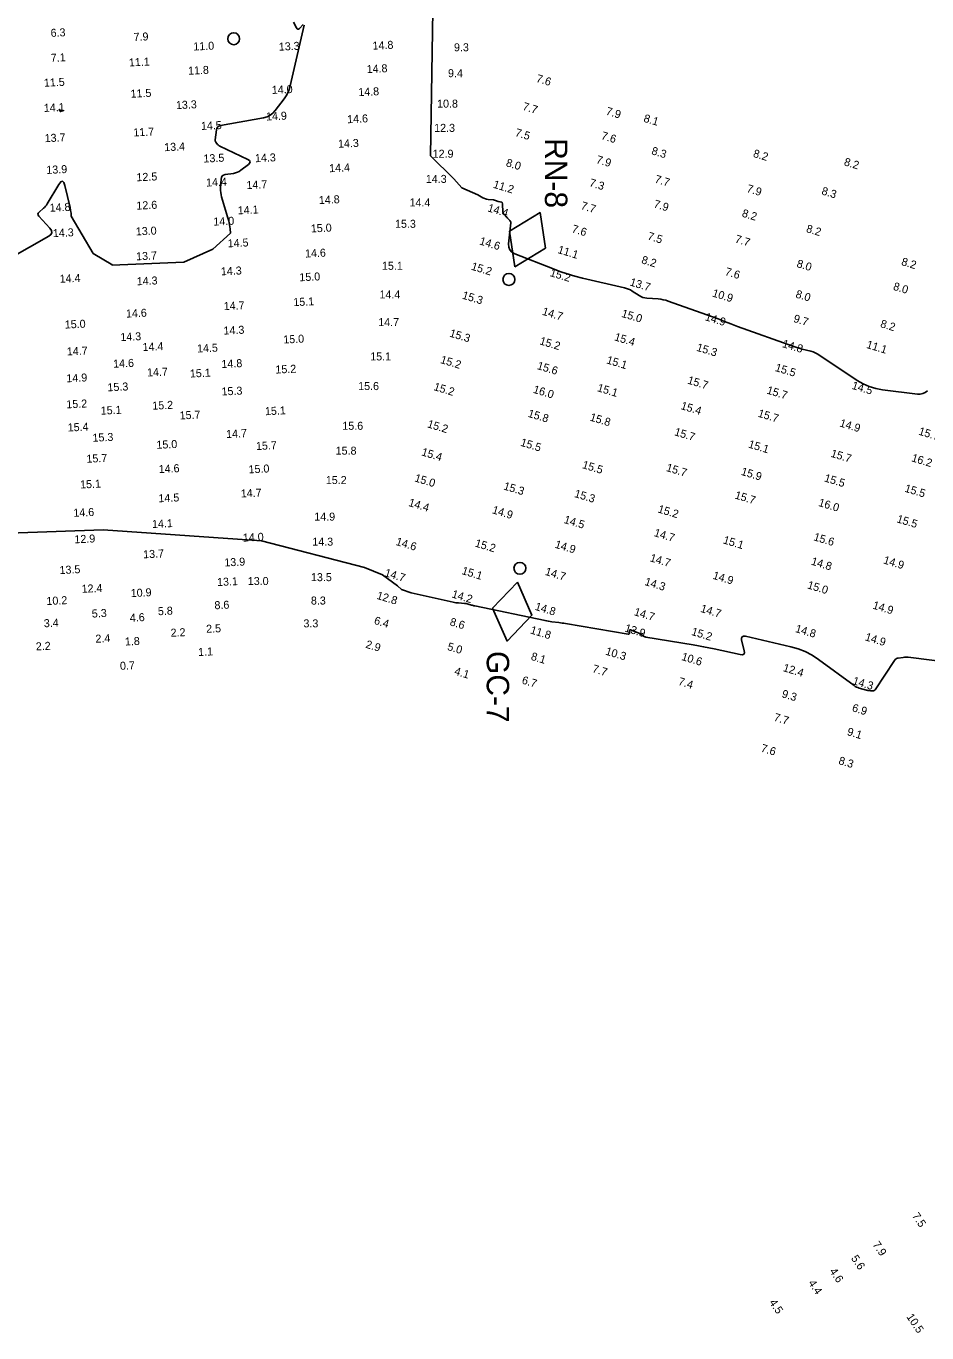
# Model space of a CAD drawing. Extents: x 824616 to 827440, y 158441 to 163197.
# Drawn here: x 825520 to 826082, y 160899 to 161716 of the extents above; entities that cross this region are included whole.
import ezdxf

# ---------------------------------------------------------------- set-up
doc = ezdxf.new("R2010")
doc.units = 0
for name, color, linetype in [('V-CHAN-CONT-EL14', 7, 'Continuous'), ('V-CHAN-NAID', 7, 'Continuous'), ('V-TOPO-SOUN', 7, 'Continuous')]:
    doc.layers.add(name, color=color, linetype=linetype)

msp = doc.modelspace()

# ---------------------------------------------------------------- linework, layer by layer
at = {"layer": 'V-CHAN-CONT-EL14'}
for points in [[(826082.79, 161487.77), (826081.39, 161486.66), (826079.87, 161485.94), (826078.21, 161485.6), (826076.43, 161485.64), (826054.58, 161488.39), (826050.41, 161489.15), (826046.4, 161490.38), (826042.58, 161492.07), (826038.92, 161494.22), (826014.97, 161510.16), (826013.79, 161510.88), (826012.55, 161511.49), (826011.27, 161512), (826009.94, 161512.4), (826004.53, 161513.78), (826003.18, 161514.14), (826001.85, 161514.53), (826000.52, 161514.95), (825999.2, 161515.4), (825964, 161527.9), (825962.99, 161528.26), (825961.99, 161528.64), (825960.99, 161529.03), (825959.99, 161529.44), (825956.02, 161531.08), (825955.02, 161531.48), (825954.02, 161531.87), (825953.02, 161532.25), (825952.01, 161532.62), (825920.83, 161543.77), (825919.29, 161544.26), (825917.74, 161544.64), (825916.16, 161544.91), (825914.56, 161545.08), (825907.5, 161545.57), (825906.22, 161545.73), (825904.99, 161546.06), (825903.81, 161546.54), (825902.68, 161547.18), (825898.27, 161550.03), (825897.15, 161550.7), (825895.98, 161551.26), (825894.77, 161551.71), (825893.51, 161552.06), (825867.23, 161558.18), (825862.45, 161559.39), (825857.73, 161560.77), (825853.06, 161562.32), (825848.44, 161564.05), (825824.94, 161573.32), (825823.08, 161574.35), (825821.82, 161575.75), (825821.16, 161577.51), (825821.1, 161579.64), (825822.45, 161592.64), (825822.45, 161593.06), (825822.37, 161593.44), (825822.19, 161593.79), (825821.93, 161594.11), (825820.72, 161595.34), (825820.42, 161595.65), (825820.12, 161595.96), (825819.82, 161596.26), (825819.52, 161596.57), (825818.27, 161597.85), (825818, 161598.18), (825817.8, 161598.54), (825817.66, 161598.94), (825817.6, 161599.36), (825817.3, 161604.5), (825817.19, 161605.27), (825816.95, 161605.57), (825816.6, 161605.59), (825815.82, 161605.69), (825814.6, 161605.98), (825813.01, 161606.53), (825811.65, 161607.12), (825808.44, 161607.29), (825807.26, 161607.53), (825805.1, 161608.2), (825801.95, 161610.13), (825791.96, 161614.57), (825786.92, 161620.15), (825772.26, 161634.63), (825774.83, 161790.45)], [(825693.47, 161716.14), (825684.63, 161678.21), (825684, 161676.04), (825683.16, 161673.96), (825682.11, 161671.99), (825680.84, 161670.11), (825675.33, 161662.81), (825673.84, 161661.16), (825672.14, 161659.87), (825670.22, 161658.93), (825668.08, 161658.35), (825641.25, 161653.49), (825640.22, 161653.16), (825639.45, 161652.59), (825638.92, 161651.79), (825638.64, 161650.74), (825637.86, 161644.61), (825637.84, 161644.19), (825637.91, 161643.8), (825638.06, 161643.43), (825638.29, 161643.08), (825639.36, 161641.72), (825639.65, 161641.4), (825639.96, 161641.12), (825640.3, 161640.88), (825640.68, 161640.67), (825658.23, 161632.21), (825659.21, 161631.56), (825659.59, 161630.85), (825659.38, 161630.07), (825658.56, 161629.22), (825653.92, 161625.55), (825652.87, 161624.82), (825651.75, 161624.26), (825650.57, 161623.84), (825649.31, 161623.59), (825644.17, 161622.87), (825643.04, 161622.56), (825642.21, 161621.96), (825641.69, 161621.08), (825641.48, 161619.92), (825641.2, 161614.25), (825641.2, 161612.88), (825641.3, 161611.52), (825641.53, 161610.18), (825641.87, 161608.85), (825645.59, 161596.47), (825646.27, 161593.95), (825646.81, 161591.41), (825647.2, 161588.84), (825647.45, 161586.24), (825636.27, 161576.11), (825618.25, 161568.05), (825573.33, 161566.25)], [(825686.71, 161718.01), (825688.55, 161714.5), (825688.95, 161713.94), (825689.4, 161713.71), (825689.89, 161713.8), (825690.44, 161714.22), (825692.7, 161716.56)], [(825509.88, 161570.53), (825533.84, 161584.26), (825535.2, 161585.32), (825535.79, 161586.51), (825535.6, 161587.82), (825534.63, 161589.25), (825527.73, 161596.89), (825527.28, 161597.54), (825527.16, 161598.18), (825527.36, 161598.79), (825527.88, 161599.39), (825530.61, 161601.73), (825531.26, 161602.34), (825531.86, 161602.99), (825532.4, 161603.69), (825532.89, 161604.44), (825540.09, 161616.57), (825541.35, 161618.24), (825542.42, 161618.7), (825543.3, 161617.94), (825543.99, 161615.96), (825547.18, 161602.17), (825547.54, 161600.41), (825547.79, 161598.63), (825547.93, 161596.85), (825561.71, 161573.54), (825573.89, 161566.27)], [(825509.14, 161398.75), (825567.91, 161400.83), (825666.87, 161393.96), (825731.09, 161377.23), (825742.31, 161372.73), (825751.81, 161365.88), (825754.26, 161363.51), (825760.32, 161361.35), (825786.55, 161355.55), (825787.35, 161355.39), (825788.16, 161355.25), (825788.97, 161355.15), (825789.79, 161355.08), (825793.59, 161354.82), (825794.14, 161354.77), (825794.69, 161354.69), (825795.22, 161354.57), (825795.76, 161354.42), (825797.88, 161353.77), (825798.42, 161353.62), (825798.95, 161353.47), (825799.49, 161353.34), (825800.03, 161353.22), (825843.88, 161344.07), (825844.95, 161343.86), (825846.01, 161343.68), (825847.08, 161343.51), (825848.16, 161343.37), (825852.46, 161342.85), (825853.54, 161342.71), (825854.61, 161342.56), (825855.68, 161342.4), (825856.75, 161342.23), (825895.89, 161335.66), (825896.21, 161335.66), (825896.43, 161335.75), (825896.57, 161335.96), (825896.61, 161336.27), (825896.62, 161337.73), (825896.67, 161338.03), (825896.79, 161338.21), (825897.01, 161338.27), (825897.31, 161338.2), (825903.01, 161336), (825903.35, 161335.85), (825903.68, 161335.68), (825903.99, 161335.48), (825904.29, 161335.26), (825905.46, 161334.34), (825905.76, 161334.13), (825906.08, 161333.96), (825906.42, 161333.83), (825906.78, 161333.75), (825936.35, 161328.85), (825939.64, 161328.29), (825942.92, 161327.69), (825946.2, 161327.04), (825949.47, 161326.36), (825965.82, 161322.87), (825967.19, 161322.76), (825968.05, 161323.15), (825968.41, 161324.02), (825968.27, 161325.38), (825966.68, 161331.8), (825966.54, 161333.16), (825966.9, 161334.02), (825967.75, 161334.39), (825969.11, 161334.27), (825997.31, 161327.76), (826001.97, 161326.44), (826006.43, 161324.66), (826010.68, 161322.44), (826014.72, 161319.77), (826036.96, 161303.44), (826037.68, 161302.96), (826038.43, 161302.54), (826039.22, 161302.2), (826040.04, 161301.93), (826044.62, 161300.62), (826044.85, 161300.56), (826045.08, 161300.51), (826045.31, 161300.47), (826045.55, 161300.44), (826046.48, 161300.32), (826046.72, 161300.3), (826046.95, 161300.28), (826047.19, 161300.27), (826047.42, 161300.27), (826049.06, 161300.27), (826049.39, 161300.31), (826049.69, 161300.42), (826049.94, 161300.6), (826050.15, 161300.86), (826062.13, 161319.16), (826062.6, 161319.74), (826063.15, 161320.18), (826063.79, 161320.49), (826064.51, 161320.67), (826067.58, 161321.09), (826068.34, 161321.17), (826069.11, 161321.2), (826069.88, 161321.18), (826070.65, 161321.11), (826098.51, 161317.75)]]:
    msp.add_lwpolyline(points, dxfattribs=at)
msp.add_lwpolyline([(825541.08, 161662.35), (825541.02, 161662.39), (825540.97, 161662.46), (825540.48, 161663.35), (825540.45, 161663.42), (825540.45, 161663.45), (825540.49, 161663.45), (825540.55, 161663.41), (825540.88, 161663.19), (825540.97, 161663.14), (825541.06, 161663.1), (825541.15, 161663.07), (825541.25, 161663.05), (825542.78, 161662.86), (825542.91, 161662.83), (825542.96, 161662.8), (825542.92, 161662.77), (825542.79, 161662.73), (825541.95, 161662.54), (825541.86, 161662.52), (825541.77, 161662.5), (825541.68, 161662.47), (825541.59, 161662.45), (825541.23, 161662.35), (825541.15, 161662.34)], close=True, dxfattribs=at)
at = {"layer": 'V-CHAN-NAID'}
for points in [[(825824.99, 161565.19), (825844.19, 161576.87), (825840.79, 161599.09), (825821.59, 161587.41)], [(825826.63, 161368.15), (825811.11, 161351.89), (825820.14, 161331.31), (825835.66, 161347.56)]]:
    msp.add_lwpolyline(points, close=True, dxfattribs=at)
for centre in [(825649.39, 161707.71), (825821.3, 161557.28), (825828.15, 161376.74)]:
    msp.add_circle(centre, 3.74, dxfattribs=at)

# ---------------------------------------------------------------- texts
for s, p in [('RN-8', (825843.82, 161645.57)), ('GC-7', (825807.45, 161325.06))]:
    msp.add_text(s, height=14, rotation=270, dxfattribs=at).set_placement(p)
at = {"layer": 'V-TOPO-SOUN'}
for s, rotation, p in [('6.3', 2.7, (825535.17, 161708.85)), ('7.9', 2.7, (825586.99, 161706.3)), ('11.0 ', 2.7, (825624.29, 161700.32)), ('13.3 ', 2.7, (825677.68, 161700.24)), ('14.8 ', 2.7, (825736.25, 161700.88)), ('7.1', 2.7, (825535.24, 161693.25)), ('11.1 ', 2.7, (825584.04, 161690.39)), ('11.8 ', 2.7, (825621.01, 161685.21)), ('14.8 ', 2.7, (825732.57, 161686.23)), ('11.5 ', 2.7, (825530.96, 161677.7)), ('7.6', 343.2, (825837.95, 161680.85)), ('11.5 ', 2.7, (825585.09, 161670.83)), ('14.0 ', 2.7, (825673.32, 161673.21)), ('14.8 ', 2.7, (825727.33, 161671.83)), ('14.1 ', 2.7, (825530.91, 161661.96)), ('13.3 ', 2.7, (825613.45, 161663.69)), ('7.7', 343.2, (825829.48, 161663.39)), ('7.9', 343.2, (825881.51, 161660.43)), ('14.5 ', 2.7, (825629.05, 161650.7)), ('14.9 ', 2.7, (825669.71, 161656.58)), ('14.6 ', 2.7, (825720.38, 161654.89)), ('8.1', 343.2, (825905.07, 161655.96)), ('13.7 ', 2.7, (825531.45, 161643.05)), ('11.7 ', 2.7, (825586.79, 161646.63)), ('7.5', 343.2, (825824.81, 161647.04)), ('7.6', 343.2, (825878.57, 161645.08)), ('13.4 ', 2.7, (825606.11, 161637.41)), ('14.3 ', 2.7, (825714.67, 161639.57)), ('8.3', 343.2, (825909.96, 161635.62)), ('13.5 ', 2.7, (825630.63, 161630.31)), ('14.3 ', 2.7, (825662.78, 161630.52)), ('8.0', 343.2, (825819.09, 161628.16)), ('7.9', 343.2, (825875.44, 161630.15)), ('8.2', 343.2, (825973.47, 161633.97)), ('8.2', 343.2, (826030.26, 161628.72)), ('13.9 ', 2.7, (825532.5, 161623.21)), ('12.5 ', 2.7, (825588.77, 161618.62)), ('14.4 ', 2.7, (825709.13, 161624.27)), ('7.7', 343.2, (825912, 161617.97)), ('14.4 ', 2.7, (825632.24, 161615.31)), ('14.7 ', 2.7, (825657.49, 161613.73)), ('11.2 ', 343.2, (825811.08, 161614.69)), ('7.3', 343.2, (825871.15, 161615.67)), ('7.9', 343.2, (825969.43, 161612.04)), ('8.3', 343.2, (826016.2, 161610.54)), ('12.6 ', 2.7, (825588.73, 161600.89)), ('14.8 ', 2.7, (825702.7, 161604.37)), ('7.7', 343.2, (825865.86, 161601.35)), ('7.9', 343.2, (825911.34, 161602.44)), ('14.8 ', 2.7, (825534.55, 161599.59)), ('14.1 ', 2.7, (825652.04, 161597.95)), ('14.4 ', 343.2, (825807.61, 161599.95)), ('8.2', 343.2, (825966.49, 161596.62)), ('13.0 ', 2.7, (825588.36, 161584.77)), ('14.0 ', 2.7, (825636.83, 161590.91)), ('15.0 ', 2.7, (825697.71, 161586.64)), ('7.6', 343.2, (825860.17, 161586.88)), ('8.2', 343.2, (826006.6, 161586.99)), ('14.3 ', 2.7, (825536.55, 161583.68)), ('14.5 ', 2.7, (825645.75, 161577.33)), ('14.6 ', 343.2, (825802.53, 161579.26)), ('7.5', 343.2, (825907.5, 161582.33)), ('7.7', 343.2, (825962.17, 161580.53)), ('13.7 ', 2.7, (825588.56, 161569.21)), ('14.6 ', 2.7, (825694.07, 161570.95)), ('11.1 ', 343.2, (825851.41, 161573.86)), ('14.3 ', 2.7, (825641.51, 161559.84)), ('15.2 ', 343.2, (825797.39, 161563.45)), ('8.2', 343.2, (825903.7, 161567.47)), ('8.0', 343.2, (826000.68, 161565.14)), ('8.2', 343.2, (826066.05, 161566.38)), ('14.4 ', 2.7, (825540.81, 161555.2)), ('14.3 ', 2.7, (825588.96, 161553.62)), ('15.0 ', 2.7, (825690.53, 161556.12)), ('15.2 ', 343.2, (825846.56, 161559.47)), ('13.7 ', 343.2, (825896.44, 161553.6)), ('7.6', 343.2, (825955.91, 161560.14)), ('15.3 ', 343.2, (825791.73, 161545.37)), ('10.9 ', 343.2, (825947.96, 161546.73)), ('8.0', 343.2, (826000.01, 161546.08)), ('8.0', 343.2, (826060.95, 161550.91)), ('14.7 ', 2.7, (825643.27, 161538.08)), ('15.1 ', 2.7, (825686.74, 161540.56)), ('14.6 ', 2.7, (825582.22, 161533.41)), ('14.7 ', 343.2, (825841.73, 161535.3)), ('15.0 ', 343.2, (825891.23, 161533.97)), ('14.9 ', 343.2, (825943.42, 161531.86)), ('9.7', 343.2, (825998.64, 161530.8)), ('15.0 ', 2.7, (825544.01, 161526.56)), ('14.3 ', 2.7, (825578.73, 161518.74)), ('14.3 ', 2.7, (825643.16, 161522.79)), ('15.3 ', 343.2, (825783.83, 161521.66)), ('8.2', 343.2, (826052.92, 161527.57)), ('14.4 ', 2.7, (825592.6, 161512.53)), ('14.5 ', 2.7, (825626.62, 161511.59)), ('15.0 ', 2.7, (825680.47, 161517.22)), ('15.2 ', 343.2, (825840.09, 161516.83)), ('15.4 ', 343.2, (825886.78, 161519.32)), ('15.3 ', 343.2, (825938.09, 161512.78)), ('14.8 ', 343.2, (825991.68, 161515.09)), ('11.1 ', 343.2, (826044.21, 161514.57)), ('14.7 ', 2.7, (825545.29, 161509.78)), ('15.2 ', 343.2, (825778.14, 161505.1)), ('15.1 ', 343.2, (825881.89, 161504.92)), ('14.6 ', 2.7, (825574.21, 161502.08)), ('14.7 ', 2.7, (825595.38, 161496.6)), ('15.1 ', 2.7, (825622.15, 161495.95)), ('14.8 ', 2.7, (825641.88, 161501.92)), ('15.2 ', 2.7, (825675.57, 161498.43)), ('15.6 ', 343.2, (825838.55, 161501.35)), ('15.5 ', 343.2, (825987.19, 161500.15)), ('14.9 ', 2.7, (825545.02, 161492.97)), ('15.3 ', 2.7, (825570.68, 161487.34)), ('15.2 ', 343.2, (825773.96, 161488.2)), ('15.1 ', 343.2, (825876.09, 161487.56)), ('15.7 ', 343.2, (825932.47, 161492.29)), ('14.5 ', 343.2, (826035.13, 161488.98)), ('15.3 ', 2.7, (825641.92, 161484.74)), ('16.0 ', 343.2, (825836.06, 161486.54)), ('15.7 ', 343.2, (825981.97, 161486.04)), ('15.2 ', 2.7, (825544.97, 161476.7)), ('15.1 ', 2.7, (825566.46, 161472.76)), ('15.2 ', 2.7, (825598.65, 161475.86)), ('15.7 ', 2.7, (825615.72, 161469.75)), ('15.1 ', 2.7, (825669.03, 161472.4)), ('15.8 ', 343.2, (825832.8, 161471.52)), ('15.4 ', 343.2, (825928.28, 161476.32)), ('15.7 ', 343.2, (825976.46, 161471.59)), ('15.4 ', 2.7, (825545.82, 161462.22)), ('15.2 ', 343.2, (825769.96, 161464.94)), ('15.8 ', 343.2, (825871.49, 161469.17)), ('14.9 ', 343.2, (826027.51, 161465.5)), ('15.3 ', 2.7, (825561.33, 161455.82)), ('14.7 ', 2.7, (825644.78, 161458.16)), ('15.7 ', 343.2, (825924.27, 161460)), ('15.7 ', 343.2, (826076.81, 161460.37)), ('15.0 ', 2.7, (825601.25, 161451.39)), ('15.7 ', 2.7, (825663.42, 161450.63)), ('15.4 ', 343.2, (825766.32, 161447.43)), ('15.5 ', 343.2, (825828.15, 161453.41)), ('15.1 ', 343.2, (825970.46, 161452.33)), ('15.7 ', 343.2, (826021.96, 161446.51)), ('15.7 ', 2.7, (825557.55, 161442.69)), ('15.5 ', 343.2, (825866.73, 161439.46)), ('16.2 ', 343.2, (826072.38, 161443.73)), ('14.6 ', 2.7, (825602.67, 161436.26)), ('15.0 ', 2.7, (825658.8, 161436.08)), ('15.0 ', 343.2, (825762, 161431.15)), ('15.7 ', 343.2, (825919.17, 161437.65)), ('15.9 ', 343.2, (825965.94, 161435.24)), ('15.5 ', 343.2, (826017.91, 161431.14)), ('15.1 ', 2.7, (825553.56, 161426.61)), ('14.7 ', 2.7, (825653.94, 161420.98)), ('15.3 ', 343.2, (825817.58, 161426.11)), ('15.5 ', 343.2, (826068.12, 161424.7)), ('14.5 ', 2.7, (825602.51, 161417.99)), ('14.4 ', 343.2, (825758.23, 161415.8)), ('15.3 ', 343.2, (825861.8, 161421.38)), ('15.7 ', 343.2, (825962.03, 161420.46)), ('16.0 ', 343.2, (826014.28, 161415.8)), ('14.6 ', 2.7, (825549.36, 161408.91)), ('14.9 ', 343.2, (825810.46, 161411.24)), ('15.2 ', 343.2, (825913.96, 161411.78)), ('14.1 ', 2.7, (825598.49, 161401.93)), ('14.5 ', 343.2, (825855.28, 161405.16)), ('15.5 ', 343.2, (826063.19, 161405.59)), ('12.9 ', 2.7, (825550.02, 161392.34)), ('14.0 ', 2.7, (825655.23, 161393.41)), ('14.6 ', 343.2, (825750.32, 161391.42)), ('15.2 ', 343.2, (825799.73, 161390.43)), ('14.9 ', 343.2, (825849.66, 161389.7)), ('14.7 ', 343.2, (825911.57, 161396.96)), ('15.1 ', 343.2, (825954.72, 161392.42)), ('15.6 ', 343.2, (826011.24, 161394.36)), ('13.7 ', 2.7, (825592.97, 161382.98)), ('14.7 ', 343.2, (825909, 161381.24)), ('13.5 ', 2.7, (825540.72, 161373.12)), ('13.9 ', 2.7, (825643.67, 161377.88)), ('15.1 ', 343.2, (825791.49, 161373.22)), ('14.8 ', 343.2, (826009.71, 161379.13)), ('14.9 ', 343.2, (826054.82, 161379.88)), ('13.1 ', 2.7, (825639.12, 161365.65)), ('14.7 ', 343.2, (825743.28, 161371.94)), ('14.7 ', 343.2, (825843.52, 161372.7)), ('14.3 ', 343.2, (825905.75, 161366.39)), ('14.9 ', 343.2, (825948.25, 161370.27)), ('12.4 ', 2.7, (825554.51, 161361.41)), ('10.9 ', 2.7, (825585.2, 161358.73)), ('12.8 ', 343.2, (825738.31, 161357.74)), ('14.2 ', 343.2, (825785.24, 161358.63)), ('15.0 ', 343.2, (826007.35, 161364.29)), ('10.2 ', 2.7, (825532.56, 161353.78)), ('5.8', 2.7, (825602.17, 161347.41)), ('8.6', 2.7, (825637.49, 161351.12)), ('14.8 ', 343.2, (825837.19, 161350.87)), ('14.7 ', 343.2, (825940.6, 161349.59)), ('14.9 ', 343.2, (826048.15, 161351.66)), ('3.4', 2.7, (825530.9, 161339.88)), ('5.3', 2.7, (825560.9, 161345.94)), ('4.6', 2.7, (825584.63, 161343.34)), ('6.4', 343.2, (825736.69, 161342.11)), ('8.6', 343.2, (825784, 161341.26)), ('14.7 ', 343.2, (825899.09, 161347.52)), ('2.2', 2.7, (825610.12, 161333.94)), ('2.5', 2.7, (825632.3, 161336.4)), ('11.8 ', 343.2, (825834.29, 161336.14)), ('13.9 ', 343.2, (825893.25, 161337.35)), ('15.2 ', 343.2, (825934.91, 161335.17)), ('14.8 ', 343.2, (825999.79, 161337.02)), ('2.2', 2.7, (825525.92, 161325.43)), ('2.4', 2.7, (825563.15, 161330.22)), ('1.8', 2.7, (825581.56, 161328.46)), ('2.9', 343.2, (825731.41, 161327.2)), ('5.0', 343.2, (825782.46, 161325.8)), ('14.9 ', 343.2, (826043.38, 161331.81)), ('1.1', 2.7, (825627.3, 161321.92)), ('8.1', 343.2, (825834.67, 161319.66)), ('10.3 ', 343.2, (825881.24, 161322.89)), ('10.6 ', 343.2, (825928.72, 161319.5)), ('0.7', 2.7, (825578.49, 161313.28)), ('4.1', 343.2, (825786.85, 161310.43)), ('7.7', 343.2, (825873, 161311.94)), ('12.4 ', 343.2, (825992.15, 161312.57)), ('6.7', 343.2, (825829.01, 161304.81)), ('7.4', 343.2, (825926.67, 161304)), ('14.3 ', 343.2, (826035.63, 161304.43)), ('9.3', 343.2, (825991.35, 161296.28)), ('6.9', 343.2, (826035.27, 161287.52)), ('7.7', 343.2, (825986.37, 161281.61)), ('9.1', 343.2, (826032.14, 161272.63)), ('7.6', 343.2, (825978.3, 161262.3)), ('8.3', 343.2, (826026.84, 161254.52)), ('7.5', 304.2, (826072.9, 160972.04)), ('7.9', 304.2, (826048.24, 160954.09)), ('5.6', 304.2, (826034.78, 160945.48)), ('4.6', 304.2, (826021.31, 160937.43)), ('4.4', 304.2, (826008.09, 160930.07)), ('4.5', 304.2, (825983.64, 160917.92)), ('10.5 ', 304.2, (826069.38, 160908.97))]:
    msp.add_text(s, height=5, rotation=rotation, dxfattribs=at).set_placement(p)
for s, p in [('9.3', (825787, 161699.89)), ('9.4', (825783.26, 161683.69)), ('10.8 ', (825776.45, 161664.66)), ('12.3 ', (825774.63, 161649.52)), ('12.9 ', (825773.67, 161633.36)), ('14.3 ', (825769.41, 161617.62)), ('14.4 ', (825759.25, 161602.9)), ('15.3 ', (825750.18, 161589.56)), ('15.1 ', (825742.01, 161563.32)), ('14.4 ', (825740.46, 161545.4)), ('14.7 ', (825739.69, 161528.11)), ('15.1 ', (825734.67, 161506.66)), ('15.6 ', (825727.15, 161488.15)), ('15.6 ', (825717.27, 161463.32)), ('15.8 ', (825713.1, 161447.79)), ('15.2 ', (825706.94, 161429.41)), ('14.9 ', (825699.74, 161406.54)), ('14.3 ', (825698.51, 161390.9)), ('13.0 ', (825658.21, 161366.3)), ('13.5 ', (825697.66, 161368.72)), ('8.3', (825697.63, 161354.11)), ('3.3', (825692.97, 161339.83))]:
    msp.add_text(s, height=5, dxfattribs=at).set_placement(p)

doc.saveas('drawing.dxf')
